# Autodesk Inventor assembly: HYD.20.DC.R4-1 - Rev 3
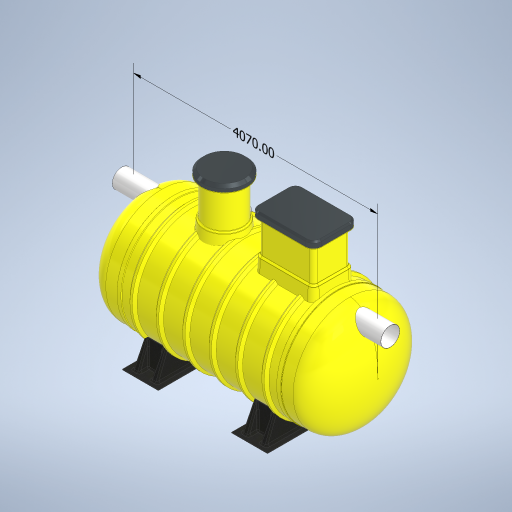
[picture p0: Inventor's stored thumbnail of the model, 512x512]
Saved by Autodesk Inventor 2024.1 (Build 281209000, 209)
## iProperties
Created: 2023-08
Part Number: HYD.20.DC.R4-1 - Rev 3
Document SubType Name: Assembly
Designer: macga
Author: macga
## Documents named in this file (43)
- D:\$ Protector Vault\Workspace\Automation Files\1. Protector Stardard Products\HydroProtectors\FAMILY\HYD.20 - Vernon\HYD.20.DC.R4-1 - Rev 3.iam
- D:\$ Protector Vault\Workspace\1. Protector Stardard Products\HydroProtectors\FAMILY\HORIZONTAL TANK - IPART\HORIZONTAL TANK - IPART.ipt
- D:\$ Protector Vault\Workspace\1. Protector Stardard Products\HydroProtectors\FAMILY\DOME - IPART\DOME - IPART\SU.DOME.1850-9.ipt
- D:\$ Protector Vault\Workspace\1. Protector Stardard Products\HydroProtectors\FAMILY\DOME - IPART\DOME - IPART.ipt
- D:\$ Protector Vault\Workspace\1. Protector Stardard Products\HydroProtectors\FAMILY\FOOT - IPART\FRP Foot - IPART\SU.HS.FOOT.1850.ipt
- D:\$ Protector Vault\Workspace\1. Protector Stardard Products\HydroProtectors\FAMILY\FOOT - IPART\FRP Foot - IPART.ipt
- D:\$ Protector Vault\Workspace\1. Protector Stardard Products\HydroProtectors\FAMILY\HYD.BAFFLE - IPART\SU.BAFFLE.1850\SU.BAFFLE.1850.ipt
- D:\$ Protector Vault\Workspace\1. Protector Stardard Products\HydroProtectors\FAMILY\HYD.BAFFLE - IPART\SU.BAFFLE.1850.ipt
- D:\$ Protector Vault\Workspace\1. Protector Stardard Products\HydroProtectors\FAMILY\ACD Base - IPART\SU.ACDBASE.1850\SU.ACDBASE.1850-300ACDFV.ipt
- D:\$ Protector Vault\Workspace\1. Protector Stardard Products\HydroProtectors\FAMILY\ACD Base - IPART\SU.ACDBASE.1850.ipt
- D:\$ Protector Vault\Workspace\1. Protector Stardard Products\HydroProtectors\FAMILY\ACDTUBE - IPART\ACDTUBE - IPART\ACDTUBE.300-1880.ipt
- D:\$ Protector Vault\Workspace\1. Protector Stardard Products\HydroProtectors\FAMILY\ACDTUBE - IPART\ACDTUBE - IPART.ipt
- D:\$ Protector Vault\Workspace\1. Protector Stardard Products\HydroProtectors\FAMILY\ACD FLOAT VALVE - IPART\ACD.FloatValve - IASSY\ACD.FVALVE.300.ASSY.iam
- D:\$ Protector Vault\Workspace\1. Protector Stardard Products\HydroProtectors\FAMILY\ACD FLOAT VALVE - IPART\ACD.FloatValve - IASSY.iam
- D:\$ Protector Vault\Workspace\1. Protector Stardard Products\HydroProtectors\FAMILY\SU.600Dia Manway Adaptor - IPART\Horizontal 600mmDia Manway Adaptor (FLANGED) SU.MWA.HS.6R-1850-1850\SU.MWA.HS.6R-1850.ipt
- D:\$ Protector Vault\Workspace\1. Protector Stardard Products\HydroProtectors\FAMILY\SU.600Dia Manway Adaptor - IPART\SU.MWA.HS.6R - IPART.ipt
- D:\$ Protector Vault\Workspace\1. Protector Stardard Products\HydroProtectors\FAMILY\WIN.600mmDiaManwayRiser - IPART\600mmDia Manway Riser.ipt
- D:\$ Protector Vault\Workspace\1. Protector Stardard Products\HydroProtectors\Automation Files\600mmDia Manway Cover.ipt
- D:\$ Protector Vault\Workspace\1. Protector Stardard Products\HydroProtectors\HYD.50 300 Outlet Vertical.ipt
- D:\$ Protector Vault\Workspace\1. Protector Stardard Products\HydroProtectors\FAMILY\OUTLET ELBOW - IPART\OUTLET ELBOW - IPART.ipt
- D:\$ Protector Vault\Workspace\1. Protector Stardard Products\HydroProtectors\Coalescer Guide Rail.ipt
- D:\$ Protector Vault\Workspace\1. Protector Stardard Products\HydroProtectors\ISO 4065 Pipe DN315x2.5xS63 - 1365.ipt
- D:\$ Protector Vault\Workspace\1. Protector Stardard Products\HydroProtectors\FAMILY\INLET PIPE ELBOW- IPART\INLET PIPE ELBOW- IPART\InletPipeElbow.300D.ipt
- D:\$ Protector Vault\Workspace\1. Protector Stardard Products\HydroProtectors\FAMILY\INLET PIPE ELBOW- IPART\INLET PIPE ELBOW- IPART.ipt
- D:\$ Protector Vault\Workspace\1. Protector Stardard Products\HydroProtectors\Upper Guide Rai Braket.ipt
- D:\$ Protector Vault\Workspace\1. Protector Stardard Products\Standard Components\Flanged Vent.ipt
- D:\$ Protector Vault\Workspace\1. Protector Stardard Products\HydroProtectors\HYD Oil Probe\Oil Probe Assembly.iam
- D:\$ Protector Vault\Workspace\1. Protector Stardard Products\Xtremeprotector\Vault\Chain.ipt
- D:\$ Protector Vault\Workspace\1. Protector Stardard Products\Xtremeprotector\Vault\Lifting Eye.ipt
- D:\$ Protector Vault\Workspace\1. Protector Stardard Products\HydroProtectors\FAMILY\OUTLET ELBOW - IPART\OUTLET ELBOW - IPART\OutletPipeElbow.300D-100DCoupling.ipt
- D:\$ Protector Vault\Workspace\1. Protector Stardard Products\HydroProtectors\FAMILY\WIN.600mmDiaManwayRiser - IPART\600mmDia Manway Riser\SU.600mmDia.ManwayRiser.600-10.ipt
- D:\$ Protector Vault\Workspace\1. Protector Stardard Products\HydroProtectors\FAMILY\Coalescer Guide Rail-014.ipt
- D:\$ Protector Vault\Workspace\Automation Files\1. Protector Stardard Products\HydroProtectors\FAMILY\CF.BASE - IPART\CF BASE SINGLE - IPART\SU.CFBASE1.1850\SU.CFBASE1.1850.SINGLE-R4.300-OP.ipt
- D:\$ Protector Vault\Workspace\Automation Files\1. Protector Stardard Products\HydroProtectors\FAMILY\CF.BASE - IPART\CF BASE SINGLE - IPART\SU.CFBASE1.1850.ipt
- D:\$ Protector Vault\Workspace\1. Protector Stardard Products\HydroProtectors\FAMILY\COALESCER FILTER - IPART\CF-R4.iam
- D:\$ Protector Vault\Workspace\1. Protector Stardard Products\Xtremeprotector\Vault\Chain\Chain-36.ipt
- D:\$ Protector Vault\Workspace\1. Protector Stardard Products\HydroProtectors\FAMILY\600x900mm Manway Adaptor - IPART\600x900mm Manway Adaptor - IPART\SU.MRADAPTOR.1850.600Lx900W.ipt
- D:\$ Protector Vault\Workspace\1. Protector Stardard Products\HydroProtectors\FAMILY\600x900mm Manway Adaptor - IPART\600x900mm Manway Adaptor - IPART.ipt
- D:\$ Protector Vault\Workspace\1. Protector Stardard Products\Standard Components\600x900 - 600mm Manway Riser.ipt
- D:\$ Protector Vault\Workspace\Automation Files\600x900mm Manway Cover ST B and D\600x900mm Manway Cover-D.ipt
- D:\$ Protector Vault\Workspace\Automation Files\600x900mm Manway Cover ST B and D.ipt
- D:\$ Protector Vault\Workspace\1. Protector Stardard Products\HydroProtectors\FAMILY\HORIZONTAL TANK - IPART\HORIZONTAL TANK - IPART\WIN.HB.1850x2720L-9.ipt
- D:\$ Protector Vault\Workspace\1. Protector Stardard Products\Trade Waste Sampling Point Assembly 300.iam
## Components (30 placed, 26 different names)
1. WIN.HB.1850x2720L-9:1
2. SU.DOME.1850-9:1 — Mate:1, Mate:3, Mate:10, Mate:88
3. SU.DOME.1850-9:2 — Mate:2, Mate:4, Angle:4
4. SU.HS.FOOT.1850:1 — Mate:5, Mate:6
5. SU.HS.FOOT.1850:2 — Mate:7, Mate:8
6. SU.BAFFLE.1850:1 — Mate:9, Mate:10, Mate:12
7. SU.ACDBASE.1850-300ACDFV:1 — Mate:11, Mate:12, Mate:13, Mate:14
8. ACDTUBE.300-1880:1 — Mate:13, Mate:14, Mate:15, Mate:38
9. ACD.FVALVE.300.ASSY:1 [sub-assembly] — Mate:15
10. SU.CFBASE1.1850.SINGLE-R4.300-OP:1
11. CF-R4:1 [sub-assembly] — Mate:18, Mate:19, Mate:76, Tangent:3, Tangent:4
12. SU.600mmDia.ManwayRiser.600-10:1 — Mate:30, Mate:31, Mate:40, Mate:41, Flush:2
13. 600mmDia Manway Cover:2 — Mate:30, Mate:31, Angle:2
14. HYD.50 300 Outlet Vertical:1 — Mate:34, Mate:35, Mate:36, Mate:37
15. OutletPipeElbow.300D-100DCoupling:2 — Mate:36, Mate:37, Mate:53, Mate:54, Angle:4
16. SU.MWA.HS.6R-1850:2
17. Coalescer Guide Rail-014:1 — Mate:47, Mate:62, Mate:63, Flush:5, Mate:83, Mate:84, Tangent:3
18. ISO 4065 Pipe DN315x2.5xS63 - 1365:2 — Mate:88
19. ISO 4065 Pipe DN315x2.5xS63 - 1365:1 — Mate:53, Mate:54, Mate:91, Mate:92
20. InletPipeElbow.300D:1
21. 600x900 - 600mm Manway Riser:1
22. 600x900mm Manway Cover-D:1 — Mate:61, Flush:4, Angle:1, Flush:13
23. Upper Guide Rai Braket:1 — Mate:62, Mate:63, Flush:5
24. Flanged Vent:2 — Mate:68, Mate:69
25. Flanged Vent:3
26. SU.MRADAPTOR.1850.600Lx900W:1
27. Oil Probe Assembly:1 [sub-assembly] — Mate:87, Flush:12, Angle:5
28. Chain-36:4 — Mate:76, Tangent:4, Tangent:5
29. Lifting Eye:1 — Mate:79, Mate:85, Mate:86, Tangent:5
30. Trade Waste Sampling Point Assembly 300:1 [sub-assembly] — Mate:91, Mate:92
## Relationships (56: Mate 44, Flush 5, Angle 4, Tangent 3)
- Mate:1: SU.DOME.1850-9:1
- Mate:2: SU.DOME.1850-9:2
- Mate:3: SU.DOME.1850-9:1
- Mate:4: SU.DOME.1850-9:2
- Mate:5: SU.HS.FOOT.1850:1
- Mate:6: SU.HS.FOOT.1850:1
- Mate:7: SU.HS.FOOT.1850:2
- Mate:8: SU.HS.FOOT.1850:2
- Mate:9: SU.BAFFLE.1850:1
- Mate:10: SU.DOME.1850-9:1 ↔ SU.BAFFLE.1850:1
- Mate:11: SU.ACDBASE.1850-300ACDFV:1
- Mate:12: SU.BAFFLE.1850:1 ↔ SU.ACDBASE.1850-300ACDFV:1
- Mate:13: SU.ACDBASE.1850-300ACDFV:1 ↔ ACDTUBE.300-1880:1
- Mate:14: SU.ACDBASE.1850-300ACDFV:1 ↔ ACDTUBE.300-1880:1
- Mate:15: ACDTUBE.300-1880:1 ↔ ACD.FVALVE.300.ASSY:1
- Mate:18: CF-R4:1
- Mate:19: CF-R4:1
- Mate:30: SU.600mmDia.ManwayRiser.600-10:1 ↔ 600mmDia Manway Cover:2
- Mate:31: SU.600mmDia.ManwayRiser.600-10:1 ↔ 600mmDia Manway Cover:2
- Mate:34: HYD.50 300 Outlet Vertical:1
- Mate:35: HYD.50 300 Outlet Vertical:1
- Mate:36: HYD.50 300 Outlet Vertical:1 ↔ OutletPipeElbow.300D-100DCoupling:2
- Mate:37: HYD.50 300 Outlet Vertical:1 ↔ OutletPipeElbow.300D-100DCoupling:2
- Mate:38: ACDTUBE.300-1880:1
- Mate:40: SU.600mmDia.ManwayRiser.600-10:1
- Mate:41: SU.600mmDia.ManwayRiser.600-10:1
- Mate:47: Coalescer Guide Rail-014:1
- Mate:53: OutletPipeElbow.300D-100DCoupling:2 ↔ ISO 4065 Pipe DN315x2.5xS63 - 1365:1
- Mate:54: OutletPipeElbow.300D-100DCoupling:2 ↔ ISO 4065 Pipe DN315x2.5xS63 - 1365:1
- Flush:2: SU.600mmDia.ManwayRiser.600-10:1
- Mate:61: 600x900mm Manway Cover-D:1
- Flush:4: 600x900mm Manway Cover-D:1
- Mate:62: Coalescer Guide Rail-014:1 ↔ Upper Guide Rai Braket:1
- Mate:63: Coalescer Guide Rail-014:1 ↔ Upper Guide Rai Braket:1
- Flush:5: Coalescer Guide Rail-014:1 ↔ Upper Guide Rai Braket:1
- Mate:68: Flanged Vent:2
- Mate:69: Flanged Vent:2
- Angle:1: 600x900mm Manway Cover-D:1
- Angle:2: 600mmDia Manway Cover:2
- Mate:76: CF-R4:1 ↔ Chain-36:4
- Mate:79: Lifting Eye:1
- Angle:4: SU.DOME.1850-9:2 ↔ OutletPipeElbow.300D-100DCoupling:2
- Mate:83: Coalescer Guide Rail-014:1
- Mate:84: Coalescer Guide Rail-014:1
- Tangent:3: CF-R4:1 ↔ Coalescer Guide Rail-014:1
- Tangent:4: CF-R4:1 ↔ Chain-36:4
- Mate:85: Lifting Eye:1
- Mate:86: Lifting Eye:1
- Tangent:5: Chain-36:4 ↔ Lifting Eye:1
- Mate:87: Oil Probe Assembly:1
- Flush:12: Oil Probe Assembly:1
- Angle:5: Oil Probe Assembly:1
- Mate:88: SU.DOME.1850-9:1 ↔ ISO 4065 Pipe DN315x2.5xS63 - 1365:2
- Flush:13: 600x900mm Manway Cover-D:1
- Mate:91: ISO 4065 Pipe DN315x2.5xS63 - 1365:1 ↔ Trade Waste Sampling Point Assembly 300:1
- Mate:92: ISO 4065 Pipe DN315x2.5xS63 - 1365:1 ↔ Trade Waste Sampling Point Assembly 300:1
